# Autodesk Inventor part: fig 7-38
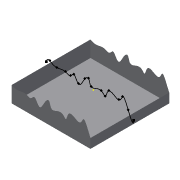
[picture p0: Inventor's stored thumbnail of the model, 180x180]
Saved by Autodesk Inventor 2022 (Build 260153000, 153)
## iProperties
Part Number: fig 7-38
Document SubType Name: Modeling
Created: 2002-12
Designer: deepak
Density: 1 g/cm^3
Material: Generic
Appearance: Default
Control State: 0
Master: False
Checked Out: False
Shininess: 64.0
Length Units: 11269
Angle Units: 11279
Time Units: 11290
Mass Units: 11283
Length Display Precision: 3
Angle Display Precision: 2
Compacted: True
Density: 0.0
Volumn: 0.0
Area: 0.0
PropertySet Name: Model Information
Author: cadcim
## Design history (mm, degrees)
sketch "Sketch1"
  geometry: L1 (-32.188, 30.089)-(27.812, 30.089); L2 (27.812, 30.089)-(27.812, -29.911); L3 (27.812, -29.911)-(-32.188, -29.911); L4 (-32.188, -29.911)-(-32.188, 30.089)
  constraints: 8 end point, 2 parallel, 1 horizontal, 1 perpendicular
  dimensions: "d0" = 60 distance of L1.start L1.end; "d1" = 60 distance of L3.end L1.start
extrude "Extrusion1" new body sketch "Sketch1" stored distance "d2" = 20; taper "d3" = 0 deg
sketch "Sketch2"
  geometry: 17 further points
  constraints: 17 other
extrude_surface "ExtrusionSrf1" sketch "Sketch2" dims "d4" = 70, "d5" = 0
split "Split1"
delete_face "Delete Face1"
node "Sketch5"
sketch "Sketch6"
  geometry: 1 further point
body "Srf1"
body "Srf2"
